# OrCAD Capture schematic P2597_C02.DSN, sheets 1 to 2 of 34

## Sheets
1 33_Buttons and Mechanical: size Custom
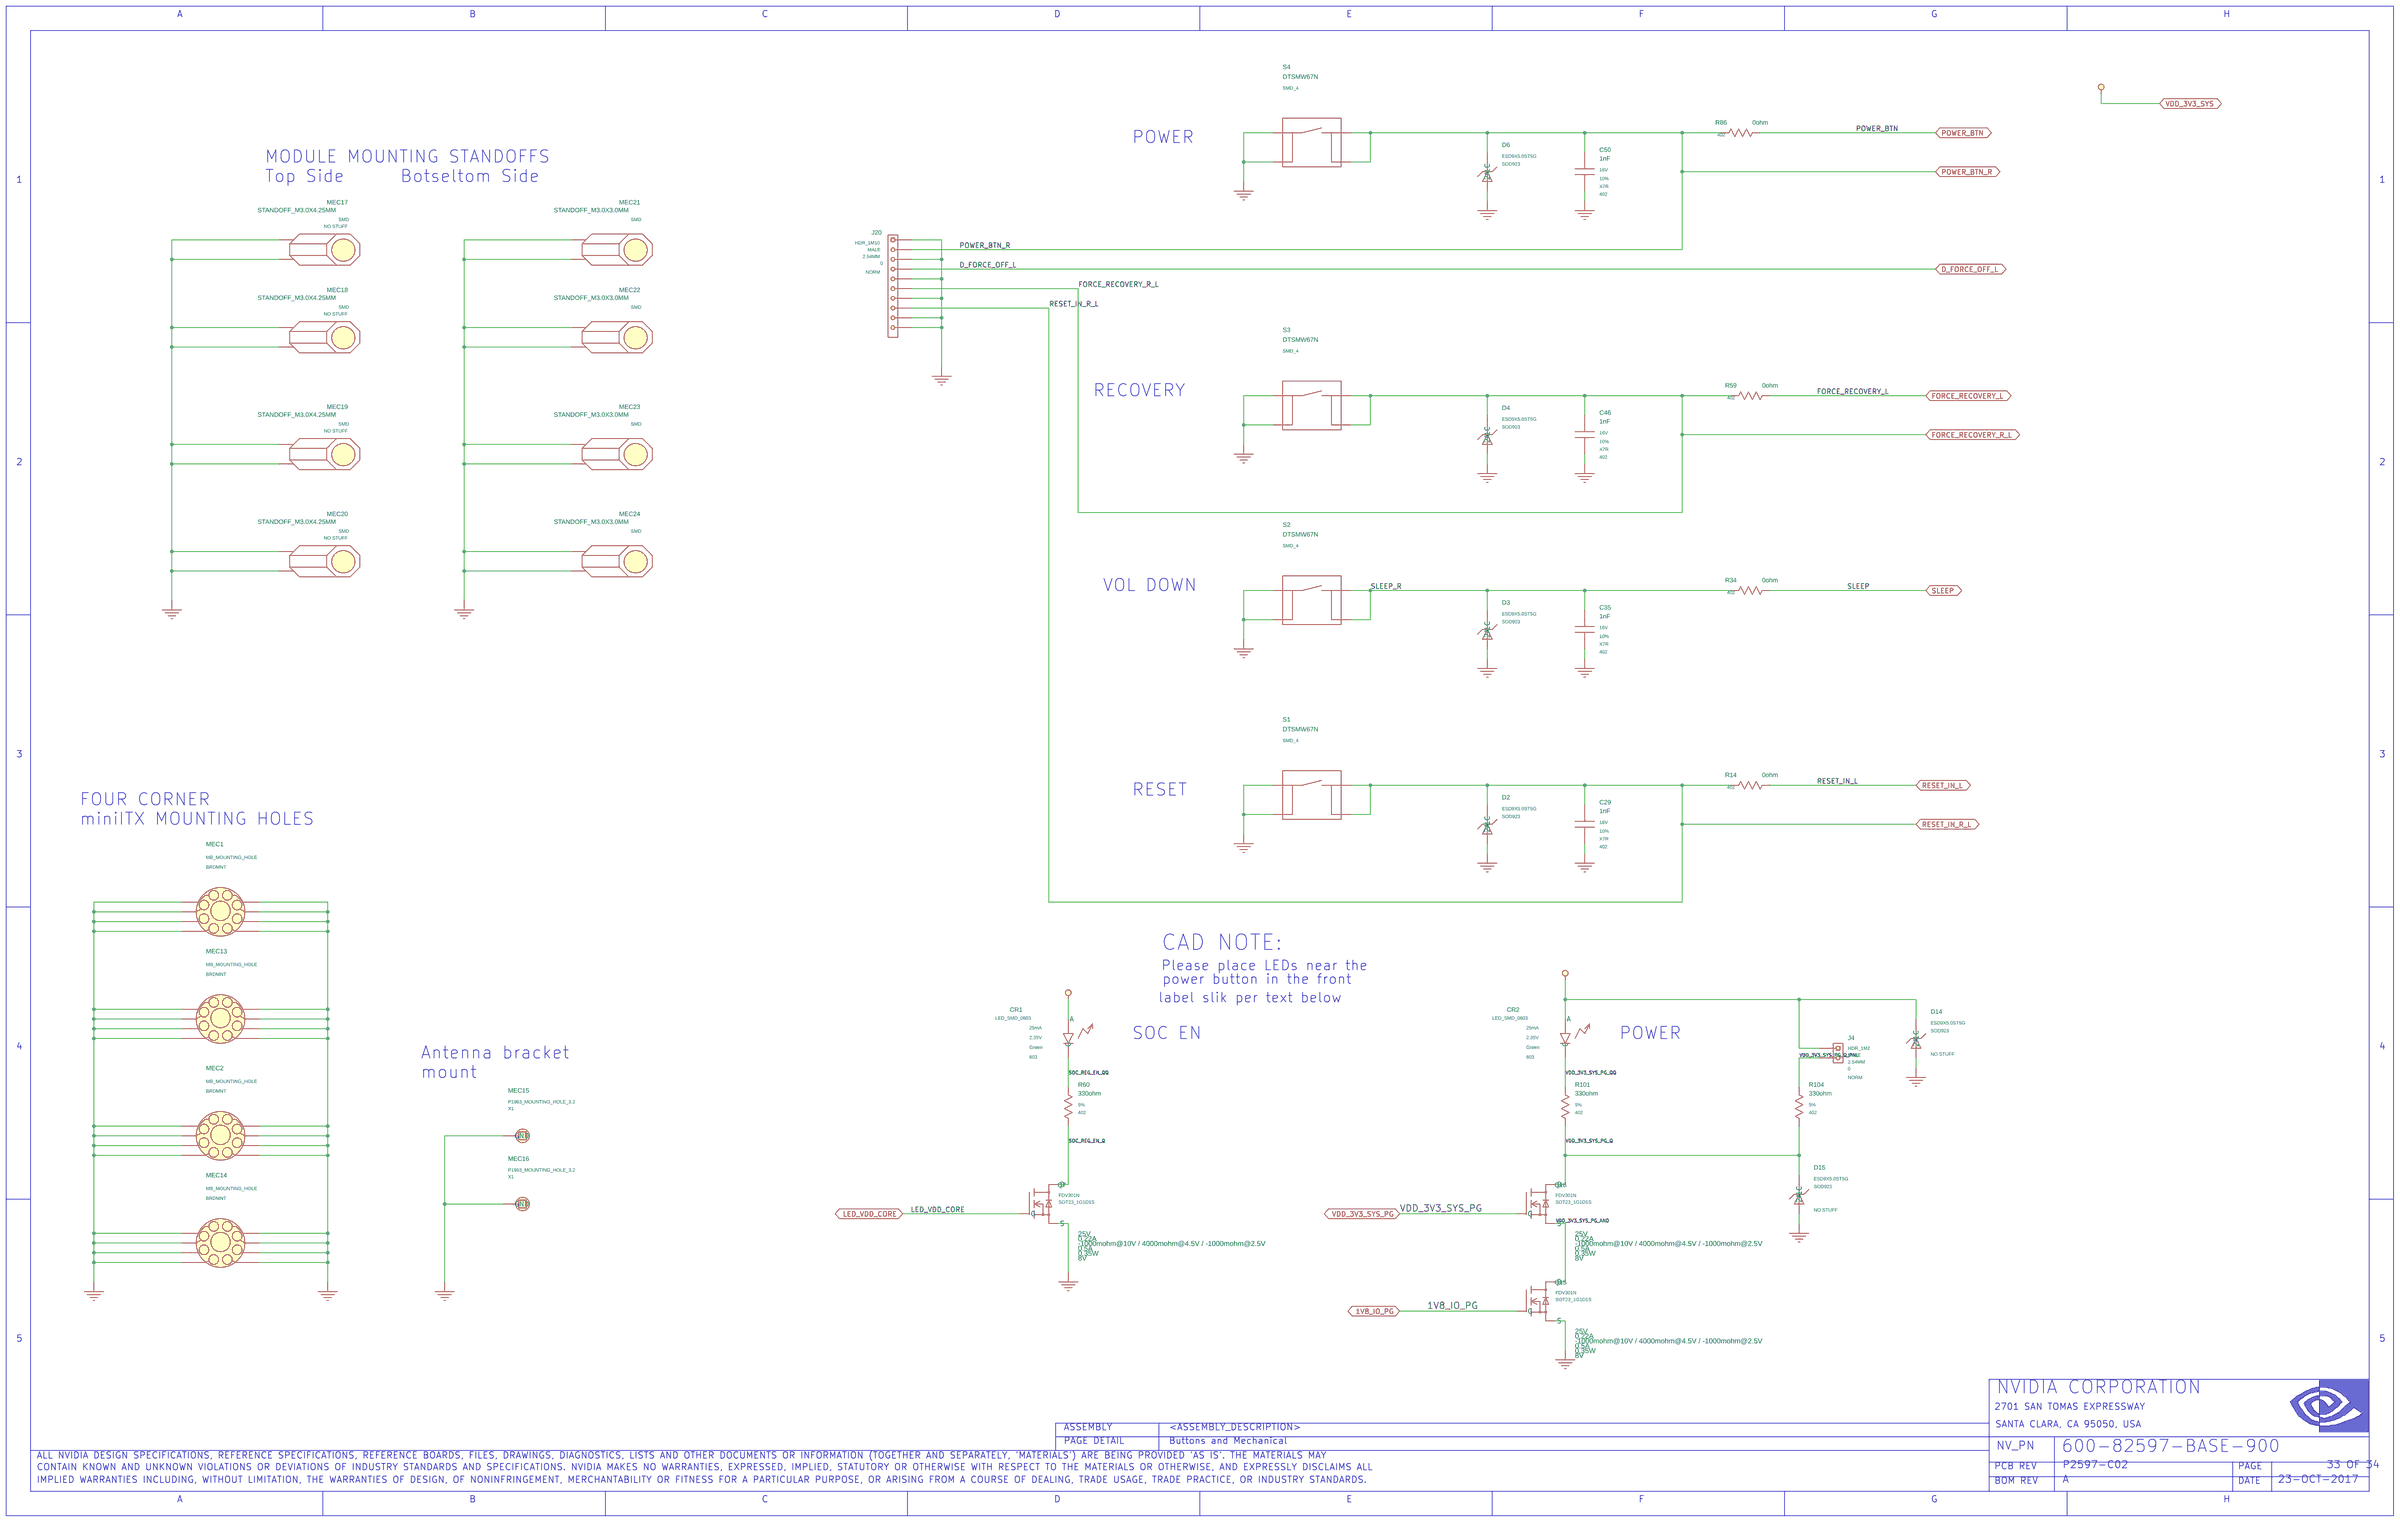
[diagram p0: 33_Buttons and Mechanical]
2 32_Power Monitor II: size Custom
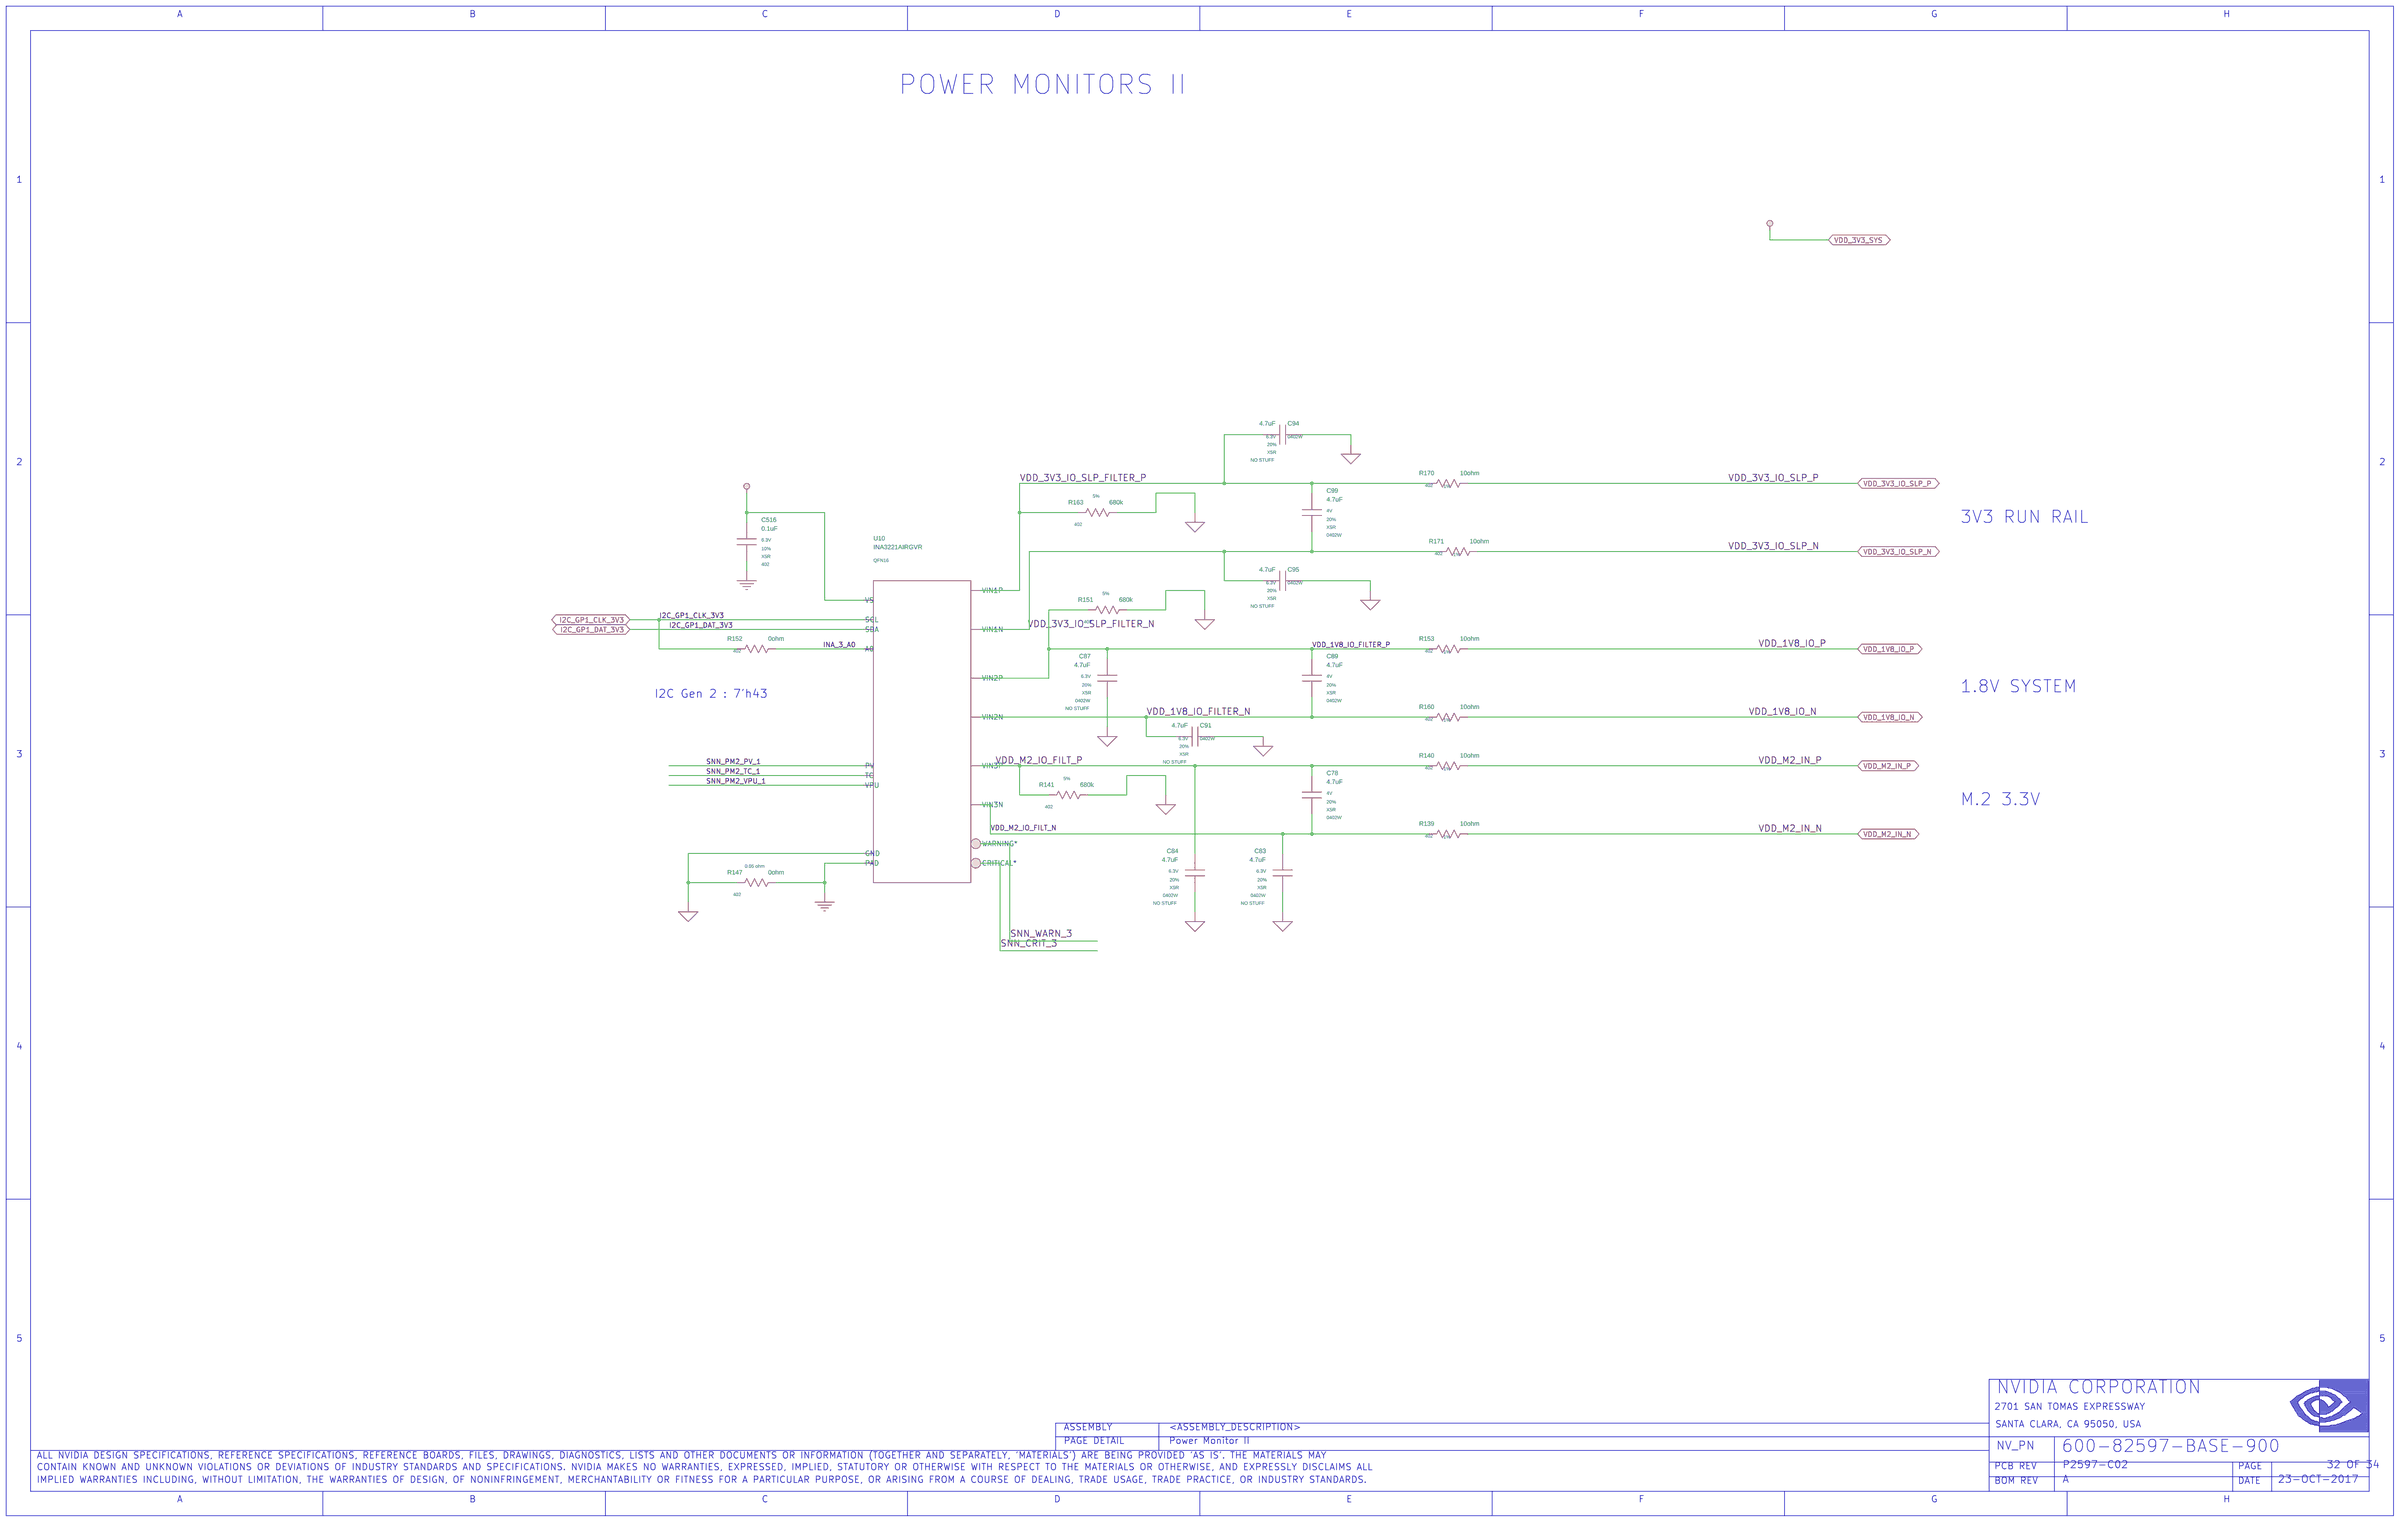
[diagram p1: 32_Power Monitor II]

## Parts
sheet 32_Power Monitor II
C78  4.7uF  [0402_LARGE]
C83  4.7uF  [0402_LARGE]
C84  4.7uF  [0402_LARGE]
C87  4.7uF  [0402_LARGE]
C89  4.7uF  [0402_LARGE]
C91  4.7uF  [0402_LARGE]
C94  4.7uF  [0402_LARGE]
C95  4.7uF  [0402_LARGE]
C99  4.7uF  [0402_LARGE]
C516  0.1uF  [402]
R139  10ohm  [402]
R140  10ohm  [402]
R141  680k  [402]
R147  0ohm  [402]
R151  680k  [402]
R152  0ohm  [402]
R153  10ohm  [402]
R160  10ohm  [402]
R163  680k  [402]
R170  10ohm  [402]
R171  10ohm  [402]
U10  U_PWRMTR_INA3221  [QFN016Q_P065_0047_T022X022]
sheet 33_Buttons and Mechanical
C29  1nF  [402]
C35  1nF  [402]
C46  1nF  [402]
C50  1nF  [402]
CR1  LED  [LED_SMD_0603_ST]
CR2  LED  [LED_SMD_0603_ST]
D2  D_ESD  [DIODE_SMD_SOD923]
D3  D_ESD  [DIODE_SMD_SOD923]
D4  D_ESD  [DIODE_SMD_SOD923]
D6  D_ESD  [DIODE_SMD_SOD923]
D14  D_ESD  [DIODE_SMD_SOD923]
D15  D_ESD  [DIODE_SMD_SOD923]
J4  HDR_1X2  [CON_HDR_001X002_TH_ST_M_P025]
J20  HDR_1X10  [CON_HDR_001X010_TH_ST_M_P025]
MEC1  MOUNTING_HOLE  [MTH_MB_C300NP156_NEW]
MEC2  MOUNTING_HOLE  [MTH_MB_C300NP156_NEW]
MEC13  MOUNTING_HOLE  [MTH_MB_C300NP156_NEW]
MEC14  MOUNTING_HOLE  [MTH_MB_C300NP156_NEW]
MEC15  MOUNTING_HOLE  [MEC_HOLE_PTH_599C_INT422C_B701C320P]
MEC16  MOUNTING_HOLE  [MEC_HOLE_PTH_599C_INT422C_B701C320P]
MEC17  MEC_STANDOFF2  [MEC_HOLE_PEM_NTH_430P]
MEC18  MEC_STANDOFF2  [MEC_HOLE_PEM_NTH_430P]
MEC19  MEC_STANDOFF2  [MEC_HOLE_PEM_NTH_430P]
MEC20  MEC_STANDOFF2  [MEC_HOLE_PEM_NTH_430P]
MEC21  MEC_STANDOFF2  [MEC_HOLE_PEM_NTH_430P]
MEC22  MEC_STANDOFF2  [MEC_HOLE_PEM_NTH_430P]
MEC23  MEC_STANDOFF2  [MEC_HOLE_PEM_NTH_430P]
MEC24  MEC_STANDOFF2  [MEC_HOLE_PEM_NTH_430P]
Q7  Q_FET_N_ENH  [SOT23]
Q15  Q_FET_N_ENH  [SOT23]
Q16  Q_FET_N_ENH  [SOT23]
R14  0ohm  [402]
R34  0ohm  [402]
R59  0ohm  [402]
R60  330ohm  [402]
R86  0ohm  [402]
R101  330ohm  [402]
R104  330ohm  [402]
S1  SW_SPST_PB  [SW_04_SMD_ST_1XONOFF_072X040]
S2  SW_SPST_PB  [SW_04_SMD_ST_1XONOFF_072X040]
S3  SW_SPST_PB  [SW_04_SMD_ST_1XONOFF_072X040]
S4  SW_SPST_PB  [SW_04_SMD_ST_1XONOFF_072X040]

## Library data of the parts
C78 = C: ASSEMBLY: PWR_MON; CDS_LIB: discrete; CDS_PART_NAME: C_0402W-4.7UF,X5R,20%,4V,039-0145-000; CDS_PHYS_PART_NAME: C_0402W-4.7UF,X5R,20%,4V,039-0145-000-039-0145-000,4.7UF; CDS_SEC: 1; DEVICE_TYPENAME: C_0402W-47UFX5R204V039-0145-000-039-0145-00047UF; DRAWING: @P2597_C02_LIB.P2597_C02(SCH_1):PAGE32; MAT: X5R; MAX_VOLTAGE: 4V; NO_XNET_CONNECTION: 1; NV_PN: 039-0145-000; PACK_TYPE: 0402W; PATH: I27; PHYS_PAGE: 32; ROT: 0; SEC: 1; SIGNAL_MODEL: DEFAULT_CAPACITOR_4.7e+06pF_2_1; TOL: 20%; VER: 1; XY: (-5450,3550)
C83 = C: ASSEMBLY: PWR_MON; CDS_LIB: discrete; CDS_PART_NAME: C_0402W-4.7UF,X5R,20%,6.3V,039-0188-000; CDS_PHYS_PART_NAME: C_0402W-4.7UF,X5R,20%,6.3V,039-0188-000-039-0188-000,4.7UF; CDS_SEC: 1; DEVICE_TYPENAME: C_0402W-47UFX5R2063V039-0188-000-039-0188-00047UF; DRAWING: @P2597_C02_LIB.P2597_C02(SCH_1):PAGE32; MAT: X5R; MAX_VOLTAGE: 6.3V; NV_PN: 039-0188-000; PACK_TYPE: 0402W; PATH: I99; PHYS_PAGE: 32; ROT: 2; SEC: 1; SEC_TYPE: 0402W; SIGNAL_MODEL: nv_cap; SKU: NO STUFF; TOL: 20%; VER: 1; XY: (-5600,3150)
C84 = C: ASSEMBLY: PWR_MON; CDS_LIB: discrete; CDS_PART_NAME: C_0402W-4.7UF,X5R,20%,6.3V,039-0188-000; CDS_PHYS_PART_NAME: C_0402W-4.7UF,X5R,20%,6.3V,039-0188-000-039-0188-000,4.7UF; CDS_SEC: 1; DEVICE_TYPENAME: C_0402W-47UFX5R2063V039-0188-000-039-0188-00047UF; DRAWING: @P2597_C02_LIB.P2597_C02(SCH_1):PAGE32; MAT: X5R; MAX_VOLTAGE: 6.3V; NV_PN: 039-0188-000; PACK_TYPE: 0402W; PATH: I98; PHYS_PAGE: 32; ROT: 2; SEC: 1; SEC_TYPE: 0402W; SIGNAL_MODEL: nv_cap; SKU: NO STUFF; TOL: 20%; VER: 1; XY: (-6050,3150)
C87 = C: ASSEMBLY: PWR_MON; CDS_LIB: discrete; CDS_PART_NAME: C_0402W-4.7UF,X5R,20%,6.3V,039-0188-000; CDS_PHYS_PART_NAME: C_0402W-4.7UF,X5R,20%,6.3V,039-0188-000-039-0188-000,4.7UF; CDS_SEC: 1; DEVICE_TYPENAME: C_0402W-47UFX5R2063V039-0188-000-039-0188-00047UF; DRAWING: @P2597_C02_LIB.P2597_C02(SCH_1):PAGE32; MAT: X5R; MAX_VOLTAGE: 6.3V; NV_PN: 039-0188-000; PACK_TYPE: 0402W; PATH: I102; PHYS_PAGE: 32; ROT: 2; SEC: 1; SEC_TYPE: 0402W; SIGNAL_MODEL: DEFAULT_CAPACITOR_100000pF_2_1; SKU: NO STUFF; TOL: 20%; VER: 1; XY: (-6500,4150)
C89 = C: ASSEMBLY: PWR_MON; CDS_LIB: discrete; CDS_PART_NAME: C_0402W-4.7UF,X5R,20%,4V,039-0145-000; CDS_PHYS_PART_NAME: C_0402W-4.7UF,X5R,20%,4V,039-0145-000-039-0145-000,4.7UF; CDS_SEC: 1; DEVICE_TYPENAME: C_0402W-47UFX5R204V039-0145-000-039-0145-00047UF; DRAWING: @P2597_C02_LIB.P2597_C02(SCH_1):PAGE32; MAT: X5R; MAX_VOLTAGE: 4V; NO_XNET_CONNECTION: 1; NV_PN: 039-0145-000; PACK_TYPE: 0402W; PATH: I28; PHYS_PAGE: 32; ROT: 0; SEC: 1; SIGNAL_MODEL: DEFAULT_CAPACITOR_4.7e+06pF_2_1; TOL: 20%; VER: 1; XY: (-5450,4150)
C91 = C#1: ASSEMBLY: PWR_MON; CDS_LIB: discrete; CDS_PART_NAME: C_0402W-4.7UF,X5R,20%,6.3V,039-0188-000; CDS_PHYS_PART_NAME: C_0402W-4.7UF,X5R,20%,6.3V,039-0188-000-039-0188-000,4.7UF; CDS_SEC: 1; CHIPS_PART_NAME: C; DEVICE_TYPENAME: C_0402W-47UFX5R2063V039-0188-000-039-0188-00047UF; DRAWING: @P2597_C02_LIB.P2597_C02(SCH_1):PAGE32; MAT: X5R; MAX_VOLTAGE: 6.3V; NV_PN: 039-0188-000; PACK_TYPE: 0402W; PATH: I103; PHYS_PAGE: 32; ROT: 2; SEC: 1; SIGNAL_MODEL: DEFAULT_CAPACITOR_100000pF_2_1; SKU: NO STUFF; TOL: 20%; VER: 2; XY: (-6050,3850)
C94 = C#1: ASSEMBLY: PWR_MON; CDS_LIB: discrete; CDS_PART_NAME: C_0402W-4.7UF,X5R,20%,6.3V,039-0188-000; CDS_PHYS_PART_NAME: C_0402W-4.7UF,X5R,20%,6.3V,039-0188-000-039-0188-000,4.7UF; CDS_SEC: 1; CHIPS_PART_NAME: C; DEVICE_TYPENAME: C_0402W-47UFX5R2063V039-0188-000-039-0188-00047UF; DRAWING: @P2597_C02_LIB.P2597_C02(SCH_1):PAGE32; MAT: X5R; MAX_VOLTAGE: 6.3V; NV_PN: 039-0188-000; PACK_TYPE: 0402W; PATH: I87; PHYS_PAGE: 32; ROT: 2; SEC: 1; SEC_TYPE: 0402W; SIGNAL_MODEL: nv_cap; SKU: NO STUFF; TOL: 20%; VER: 2; XY: (-5600,5400)
C95 = C#1: ASSEMBLY: PWR_MON; CDS_LIB: discrete; CDS_PART_NAME: C_0402W-4.7UF,X5R,20%,6.3V,039-0188-000; CDS_PHYS_PART_NAME: C_0402W-4.7UF,X5R,20%,6.3V,039-0188-000-039-0188-000,4.7UF; CDS_SEC: 1; CHIPS_PART_NAME: C; DEVICE_TYPENAME: C_0402W-47UFX5R2063V039-0188-000-039-0188-00047UF; DRAWING: @P2597_C02_LIB.P2597_C02(SCH_1):PAGE32; MAT: X5R; MAX_VOLTAGE: 6.3V; NV_PN: 039-0188-000; PACK_TYPE: 0402W; PATH: I88; PHYS_PAGE: 32; ROT: 2; SEC: 1; SIGNAL_MODEL: DEFAULT_CAPACITOR_100000pF_2_1; SKU: NO STUFF; TOL: 20%; VER: 2; XY: (-5600,4650)
C99 = C: ASSEMBLY: PWR_MON; CDS_LIB: discrete; CDS_PART_NAME: C_0402W-4.7UF,X5R,20%,4V,039-0145-000; CDS_PHYS_PART_NAME: C_0402W-4.7UF,X5R,20%,4V,039-0145-000-039-0145-000,4.7UF; CDS_SEC: 1; DEVICE_TYPENAME: C_0402W-47UFX5R204V039-0145-000-039-0145-00047UF; DRAWING: @P2597_C02_LIB.P2597_C02(SCH_1):PAGE32; MAT: X5R; MAX_VOLTAGE: 4V; NO_XNET_CONNECTION: 1; NV_PN: 039-0145-000; PACK_TYPE: 0402W; PATH: I32; PHYS_PAGE: 32; ROT: 0; SEC: 1; SEC_TYPE: 0402W; SIGNAL_MODEL: DEFAULT_CAPACITOR_4.7e+06pF_2_1; TOL: 20%; VER: 1; XY: (-5450,5000)
C516 = C: ASSEMBLY: PWR_MON; CDS_LIB: discrete; CDS_PART_NAME: C_0402-0.1UF,X5R,10%,6.3V,039-0007-000; CDS_PHYS_PART_NAME: C_0402-0.1UF,X5R,10%,6.3V,039-0007-000-0.1UF,039-0007-000; CDS_SEC: 1; DEVICE_TYPENAME: C_0402-01UFX5R1063V039-0007-000-01UF039-0007-000; DRAWING: @P2597_C02_LIB.P2597_C02(SCH_1):PAGE32; MAT: X5R; MAX_VOLTAGE: 6.3V; NV_PN: 039-0007-000; PATH: I7; PHYS_PAGE: 32; ROT: 0; SEC: 1; SIGNAL_MODEL: DEFAULT_CAPACITOR_100000pF_2_1; TOL: 10%; VER: 1; XY: (-8350,4850)
R139 = R: ASSEMBLY: PWR_MON; CDS_LIB: discrete; CDS_PART_NAME: R_0402-10OHM,1 %,62.5MW,195-0001-000; CDS_PHYS_PART_NAME: R_0402-10OHM,1 %,62.5MW,195-0001-000-10OHM,195-0001-000; CDS_SEC: 1; DEVICE_TYPENAME: R_0402-10OHM1625MW195-0001-000-10OHM195-0001-000; DRAWING: @P2597_C02_LIB.P2597_C02(SCH_1):PAGE32; MAX_WATTAGE: 62.5mW; NV_PN: 195-0001-000; PATH: I26; PHYS_PAGE: 32; ROT: 0; SEC: 1; SIGNAL_MODEL: nv_res; TOL: 1%; VER: 1; XY: (-4750,3350)
R140 = R: ASSEMBLY: PWR_MON; CDS_LIB: discrete; CDS_PART_NAME: R_0402-10OHM,1 %,62.5MW,195-0001-000; CDS_PHYS_PART_NAME: R_0402-10OHM,1 %,62.5MW,195-0001-000-10OHM,195-0001-000; CDS_SEC: 1; DEVICE_TYPENAME: R_0402-10OHM1625MW195-0001-000-10OHM195-0001-000; DRAWING: @P2597_C02_LIB.P2597_C02(SCH_1):PAGE32; MAX_WATTAGE: 62.5mW; NV_PN: 195-0001-000; PATH: I29; PHYS_PAGE: 32; ROT: 0; SEC: 1; SIGNAL_MODEL: nv_res; TOL: 1%; VER: 1; XY: (-4750,3700)
R141 = R: ASSEMBLY: PWR_MON; CDS_LIB: discrete; CDS_PART_NAME: R_0402-680K,5 %,62.5MW,195-0628-000; CDS_PHYS_PART_NAME: R_0402-680K,5 %,62.5MW,195-0628-000-195-0628-000,680K; CDS_SEC: 1; DEVICE_TYPENAME: R_0402-680K5625MW195-0628-000-195-0628-000680K; DRAWING: @P2597_C02_LIB.P2597_C02(SCH_1):PAGE32; MAX_WATTAGE: 62.5mW; NV_PN: 195-0628-000; PATH: I120; PHYS_PAGE: 32; ROT: 0; SEC: 1; SIGNAL_MODEL: nv_res; TOL: 5%; VER: 1; XY: (-6700,3550)
R147 = R: ASSEMBLY: PWR_MON; CDS_LIB: discrete; CDS_PART_NAME: R_0402-0OHM,0.05 OHM,62.5MW,195-2655-000; CDS_PHYS_PART_NAME: R_0402-0OHM,0.05 OHM,62.5MW,195-2655-000-0OHM,195-2655-000; CDS_SEC: 1; DEVICE_TYPENAME: R_0402-0OHM005OHM625MW195-2655-000-0OHM195-2655-000; DRAWING: @P2597_C02_LIB.P2597_C02(SCH_1):PAGE32; MAX_WATTAGE: 62.5mW; NV_PN: 195-2655-000; PATH: I95; PHYS_PAGE: 32; ROT: 0; SEC: 1; SIGNAL_MODEL: nv_res; TOL: 0.05 ohm; VER: 1; XY: (-8300,3100)
R151 = R: ASSEMBLY: PWR_MON; CDS_LIB: discrete; CDS_PART_NAME: R_0402-680K,5 %,62.5MW,195-0628-000; CDS_PHYS_PART_NAME: R_0402-680K,5 %,62.5MW,195-0628-000-195-0628-000,680K; CDS_SEC: 1; DEVICE_TYPENAME: R_0402-680K5625MW195-0628-000-195-0628-000680K; DRAWING: @P2597_C02_LIB.P2597_C02(SCH_1):PAGE32; MAX_WATTAGE: 62.5mW; NV_PN: 195-0628-000; PATH: I118; PHYS_PAGE: 32; ROT: 0; SEC: 1; SIGNAL_MODEL: nv_res; TOL: 5%; VER: 1; XY: (-6500,4500)
R152 = R: ASSEMBLY: PWR_MON; CDS_LIB: discrete; CDS_PART_NAME: R_0402-0OHM,0.05 OHM,62.5MW,195-2655-000; CDS_PHYS_PART_NAME: R_0402-0OHM,0.05 OHM,62.5MW,195-2655-000-0OHM,195-2655-000; CDS_SEC: 1; DEVICE_TYPENAME: R_0402-0OHM005OHM625MW195-2655-000-0OHM195-2655-000; DRAWING: @P2597_C02_LIB.P2597_C02(SCH_1):PAGE32; MAX_WATTAGE: 62.5mW; NV_PN: 195-2655-000; PATH: I108; PHYS_PAGE: 32; ROT: 0; SEC: 1; SIGNAL_MODEL: nv_res; TOL: 0.05 ohm; VER: 1; XY: (-8300,4300)
R153 = R: ASSEMBLY: PWR_MON; CDS_LIB: discrete; CDS_PART_NAME: R_0402-10OHM,1 %,62.5MW,195-0001-000; CDS_PHYS_PART_NAME: R_0402-10OHM,1 %,62.5MW,195-0001-000-10OHM,195-0001-000; CDS_SEC: 1; DEVICE_TYPENAME: R_0402-10OHM1625MW195-0001-000-10OHM195-0001-000; DRAWING: @P2597_C02_LIB.P2597_C02(SCH_1):PAGE32; MAX_WATTAGE: 62.5mW; NV_PN: 195-0001-000; PATH: I31; PHYS_PAGE: 32; ROT: 0; SEC: 1; SIGNAL_MODEL: nv_res; TOL: 1%; VER: 1; XY: (-4750,4300)
R160 = R: ASSEMBLY: PWR_MON; CDS_LIB: discrete; CDS_PART_NAME: R_0402-10OHM,1 %,62.5MW,195-0001-000; CDS_PHYS_PART_NAME: R_0402-10OHM,1 %,62.5MW,195-0001-000-10OHM,195-0001-000; CDS_SEC: 1; DEVICE_TYPENAME: R_0402-10OHM1625MW195-0001-000-10OHM195-0001-000; DRAWING: @P2597_C02_LIB.P2597_C02(SCH_1):PAGE32; MAX_WATTAGE: 62.5mW; NV_PN: 195-0001-000; PATH: I30; PHYS_PAGE: 32; ROT: 0; SEC: 1; SIGNAL_MODEL: nv_res; TOL: 1%; VER: 1; XY: (-4750,3950)
R163 = R: ASSEMBLY: PWR_MON; CDS_LIB: discrete; CDS_PART_NAME: R_0402-680K,5 %,62.5MW,195-0628-000; CDS_PHYS_PART_NAME: R_0402-680K,5 %,62.5MW,195-0628-000-195-0628-000,680K; CDS_SEC: 1; DEVICE_TYPENAME: R_0402-680K5625MW195-0628-000-195-0628-000680K; DRAWING: @P2597_C02_LIB.P2597_C02(SCH_1):PAGE32; MAX_WATTAGE: 62.5mW; NV_PN: 195-0628-000; PATH: I115; PHYS_PAGE: 32; ROT: 0; SEC: 1; SIGNAL_MODEL: nv_res; TOL: 5%; VER: 1; XY: (-6550,5000)
R170 = R: ASSEMBLY: PWR_MON; CDS_LIB: discrete; CDS_PART_NAME: R_0402-10OHM,1 %,62.5MW,195-0001-000; CDS_PHYS_PART_NAME: R_0402-10OHM,1 %,62.5MW,195-0001-000-10OHM,195-0001-000; CDS_SEC: 1; DEVICE_TYPENAME: R_0402-10OHM1625MW195-0001-000-10OHM195-0001-000; DRAWING: @P2597_C02_LIB.P2597_C02(SCH_1):PAGE32; MAX_WATTAGE: 62.5mW; NV_PN: 195-0001-000; PATH: I34; PHYS_PAGE: 32; ROT: 0; SEC: 1; SIGNAL_MODEL: nv_res; TOL: 1%; VER: 1; XY: (-4750,5150)
R171 = R: ASSEMBLY: PWR_MON; CDS_LIB: discrete; CDS_PART_NAME: R_0402-10OHM,1 %,62.5MW,195-0001-000; CDS_PHYS_PART_NAME: R_0402-10OHM,1 %,62.5MW,195-0001-000-10OHM,195-0001-000; CDS_SEC: 1; DEVICE_TYPENAME: R_0402-10OHM1625MW195-0001-000-10OHM195-0001-000; DRAWING: @P2597_C02_LIB.P2597_C02(SCH_1):PAGE32; MAX_WATTAGE: 62.5mW; NV_PN: 195-0001-000; PATH: I33; PHYS_PAGE: 32; ROT: 0; SEC: 1; SIGNAL_MODEL: nv_res; TOL: 1%; VER: 1; XY: (-4700,4800)
U10 = U_PWRMTR_INA3221: ASSEMBLY: PWR_MON; CDS_LIB: digital; CDS_PART_NAME: U_PWRMTR_INA3221_QFN16-INA3221AIRGVR,-9999V..9999V,-9999V..9999V,9999A,MONITOR,115-1066-000; CDS_PHYS_PART_NAME: U_PWRMTR_INA3221_QFN16-INA3221AIRGVR,-9999V..9999V,-9999V..9999V,9999A,MONITOR,115-1066-000-115-1066-000; CDS_SEC: 1; DEVICE_TYPENAME: U_PWRMTR_INA3221_QFN16-INA3221AIRGVR-9999V9999V-9999V9999V9999AMONITOR115-1066-000-115-1066-000; DRAWING: @P2597_C02_LIB.P2597_C02(SCH_1):PAGE32; MAX_CURRENT: 9999A; MAX_VOLTAGE: -9999V..9999V; NV_NAME: INA3221AIRGVR; NV_PN: 115-1066-000; OUTPUT_VOLTAGE: -9999V..9999V; PACK_TYPE: QFN16; PATH: I5; PHYS_PAGE: 32; ROT: 0; SEC: 1; SEC_TYPE: QFN16; TYPE: Monitor; VER: 1; XY: (-7450,3900)
C29 = C: ASSEMBLY: BUTTONS; CDS_LIB: discrete; CDS_PART_NAME: C_0402-1NF,X7R,10%,16V,036-0012-000; CDS_PHYS_PART_NAME: C_0402-1NF,X7R,10%,16V,036-0012-000-036-0012-000,1NF; CDS_SEC: 1; DEVICE_TYPENAME: C_0402-1NFX7R1016V036-0012-000-036-0012-0001NF; DRAWING: @P2597_C02_LIB.P2597_C02(SCH_1):PAGE33; MAT: X7R; MAX_VOLTAGE: 16V; NV_PN: 036-0012-000; PATH: I36; PHYS_PAGE: 33; ROT: 0; SEC: 1; SIGNAL_MODEL: nv_cap; TOL: 10%; VER: 1; XY: (-4050,3400)
C35 = C: ASSEMBLY: BUTTONS; CDS_LIB: discrete; CDS_PART_NAME: C_0402-1NF,X7R,10%,16V,036-0012-000; CDS_PHYS_PART_NAME: C_0402-1NF,X7R,10%,16V,036-0012-000-036-0012-000,1NF; CDS_SEC: 1; DEVICE_TYPENAME: C_0402-1NFX7R1016V036-0012-000-036-0012-0001NF; DRAWING: @P2597_C02_LIB.P2597_C02(SCH_1):PAGE33; MAT: X7R; MAX_VOLTAGE: 16V; NV_PN: 036-0012-000; PATH: I102; PHYS_PAGE: 33; ROT: 0; SEC: 1; SIGNAL_MODEL: DEFAULT_CAPACITOR_1000pF_2_1; TOL: 10%; VER: 1; XY: (-4050,4400)
C46 = C: ASSEMBLY: BUTTONS; CDS_LIB: discrete; CDS_PART_NAME: C_0402-1NF,X7R,10%,16V,036-0012-000; CDS_PHYS_PART_NAME: C_0402-1NF,X7R,10%,16V,036-0012-000-036-0012-000,1NF; CDS_SEC: 1; DEVICE_TYPENAME: C_0402-1NFX7R1016V036-0012-000-036-0012-0001NF; DRAWING: @P2597_C02_LIB.P2597_C02(SCH_1):PAGE33; MAT: X7R; MAX_VOLTAGE: 16V; NV_PN: 036-0012-000; PATH: I30; PHYS_PAGE: 33; ROT: 0; SEC: 1; SIGNAL_MODEL: DEFAULT_CAPACITOR_1000pF_2_1; TOL: 10%; VER: 1; XY: (-4050,5400)
C50 = C: ASSEMBLY: BUTTONS; CDS_LIB: discrete; CDS_PART_NAME: C_0402-1NF,X7R,10%,16V,036-0012-000; CDS_PHYS_PART_NAME: C_0402-1NF,X7R,10%,16V,036-0012-000-036-0012-000,1NF; CDS_SEC: 1; DEVICE_TYPENAME: C_0402-1NFX7R1016V036-0012-000-036-0012-0001NF; DRAWING: @P2597_C02_LIB.P2597_C02(SCH_1):PAGE33; MAT: X7R; MAX_VOLTAGE: 16V; NV_PN: 036-0012-000; PATH: I18; PHYS_PAGE: 33; ROT: 0; SEC: 1; SIGNAL_MODEL: nv_cap; TOL: 10%; VER: 1; XY: (-4050,6750)
CR1 = LED: ASSEMBLY: BUTTONS; CDS_LIB: discrete; CDS_PART_NAME: LED_0603-LED_SMD_0603,5V,60MA,2.35V,25MA,GREEN,092-0073-000; CDS_PHYS_PART_NAME: LED_0603-LED_SMD_0603,5V,60MA,2.35V,25MA,GREEN,092-0073-000-092-0073-000; CDS_SEC: 1; CONTINUOUS_CURRENT: 25mA; DEVICE_TYPENAME: LED_0603-LED_SMD_06035V60MA235V25MAGREEN092-0073-000-092-0073-000; DRAWING: @P2597_C02_LIB.P2597_C02(SCH_1):PAGE33; FORWARD_VOLTAGE: 2.35V; MAX_CURRENT: 60mA; MAX_VOLTAGE: 5V; NV_COLOR: Green; NV_NAME: LED_SMD_0603; NV_PN: 092-0073-000; PACK_TYPE: 603; PATH: I75; PHYS_PAGE: 33; ROT: 0; SEC: 1; SEC_TYPE: 603; VER: 1; XY: (-6700,2300)
CR2 = LED: ASSEMBLY: BUTTONS; CDS_LIB: discrete; CDS_PART_NAME: LED_0603-LED_SMD_0603,5V,60MA,2.35V,25MA,GREEN,092-0073-000; CDS_PHYS_PART_NAME: LED_0603-LED_SMD_0603,5V,60MA,2.35V,25MA,GREEN,092-0073-000-092-0073-000; CDS_SEC: 1; CONTINUOUS_CURRENT: 25mA; DEVICE_TYPENAME: LED_0603-LED_SMD_06035V60MA235V25MAGREEN092-0073-000-092-0073-000; DRAWING: @P2597_C02_LIB.P2597_C02(SCH_1):PAGE33; FORWARD_VOLTAGE: 2.35V; MAX_CURRENT: 60mA; MAX_VOLTAGE: 5V; NV_COLOR: Green; NV_NAME: LED_SMD_0603; NV_PN: 092-0073-000; PACK_TYPE: 603; PATH: I52; PHYS_PAGE: 33; ROT: 0; SEC: 1; SEC_TYPE: 603; VER: 1; XY: (-4150,2300)
D2 = D_ESD#1: ASSEMBLY: BUTTONS; BREAKDOWN_VOLTAGE_MIN_TYP: 6.2V; CAPACITANCE_MAX_TYP: 65pF; CDS_LIB: discrete; CDS_PART_NAME: D_ESD_SOD923-ESD9X5.0ST5G,1 LINE,UNI-DIRECTIONAL,5V,1UA,6.2V,12.3V@8.7A,65PF,090-0134-000; CDS_PHYS_PART_NAME: D_ESD_SOD923-ESD9X5.0ST5G,1 LINE,UNI-DIRECTIONAL,5V,1UA,6.2V,12.3V@8.7A,65PF,090-0134-000-090-0134-000; CDS_SEC: 1; CLAMPING_VOLTAGE: 12.3V@8.7A; CONFIGURATION: 1 Line; DEVICE_TYPENAME: D_ESD_SOD923-ESD9X50ST5G1LINEUNI-DIRECTIONAL5V1UA62V123V87A65PF090-0134-000-090-0134-000; DRAWING: @P2597_C02_LIB.P2597_C02(SCH_1):PAGE33; MAX_REVERSE_LEAKAGE_CURRENT: 1uA; MAX_REVERSE_VOLTAGE: 5V; NV_NAME: ESD9X5.0ST5G; NV_PN: 090-0134-000; PACK_TYPE: SOD923; PATH: I38; PHYS_PAGE: 33; POLARITY: Uni-Directional; ROT: 0; SEC: 1; VER: 5; XY: (-4550,3400)
D3 = D_ESD#1: ASSEMBLY: BUTTONS; BREAKDOWN_VOLTAGE_MIN_TYP: 6.2V; CAPACITANCE_MAX_TYP: 65pF; CDS_LIB: discrete; CDS_PART_NAME: D_ESD_SOD923-ESD9X5.0ST5G,1 LINE,UNI-DIRECTIONAL,5V,1UA,6.2V,12.3V@8.7A,65PF,090-0134-000; CDS_PHYS_PART_NAME: D_ESD_SOD923-ESD9X5.0ST5G,1 LINE,UNI-DIRECTIONAL,5V,1UA,6.2V,12.3V@8.7A,65PF,090-0134-000-090-0134-000; CDS_SEC: 1; CLAMPING_VOLTAGE: 12.3V@8.7A; CONFIGURATION: 1 Line; DEVICE_TYPENAME: D_ESD_SOD923-ESD9X50ST5G1LINEUNI-DIRECTIONAL5V1UA62V123V87A65PF090-0134-000-090-0134-000; DRAWING: @P2597_C02_LIB.P2597_C02(SCH_1):PAGE33; MAX_REVERSE_LEAKAGE_CURRENT: 1uA; MAX_REVERSE_VOLTAGE: 5V; NV_NAME: ESD9X5.0ST5G; NV_PN: 090-0134-000; PACK_TYPE: SOD923; PATH: I105; PHYS_PAGE: 33; POLARITY: Uni-Directional; ROT: 0; SEC: 1; VER: 5; XY: (-4550,4400)
D4 = D_ESD#1: ASSEMBLY: BUTTONS; BREAKDOWN_VOLTAGE_MIN_TYP: 6.2V; CAPACITANCE_MAX_TYP: 65pF; CDS_LIB: discrete; CDS_PART_NAME: D_ESD_SOD923-ESD9X5.0ST5G,1 LINE,UNI-DIRECTIONAL,5V,1UA,6.2V,12.3V@8.7A,65PF,090-0134-000; CDS_PHYS_PART_NAME: D_ESD_SOD923-ESD9X5.0ST5G,1 LINE,UNI-DIRECTIONAL,5V,1UA,6.2V,12.3V@8.7A,65PF,090-0134-000-090-0134-000; CDS_SEC: 1; CLAMPING_VOLTAGE: 12.3V@8.7A; CONFIGURATION: 1 Line; DEVICE_TYPENAME: D_ESD_SOD923-ESD9X50ST5G1LINEUNI-DIRECTIONAL5V1UA62V123V87A65PF090-0134-000-090-0134-000; DRAWING: @P2597_C02_LIB.P2597_C02(SCH_1):PAGE33; MAX_REVERSE_LEAKAGE_CURRENT: 1uA; MAX_REVERSE_VOLTAGE: 5V; NV_NAME: ESD9X5.0ST5G; NV_PN: 090-0134-000; PACK_TYPE: SOD923; PATH: I28; PHYS_PAGE: 33; POLARITY: Uni-Directional; ROT: 0; SEC: 1; VER: 5; XY: (-4550,5400)
D6 = D_ESD#1: ASSEMBLY: BUTTONS; BREAKDOWN_VOLTAGE_MIN_TYP: 6.2V; CAPACITANCE_MAX_TYP: 65pF; CDS_LIB: discrete; CDS_PART_NAME: D_ESD_SOD923-ESD9X5.0ST5G,1 LINE,UNI-DIRECTIONAL,5V,1UA,6.2V,12.3V@8.7A,65PF,090-0134-000; CDS_PHYS_PART_NAME: D_ESD_SOD923-ESD9X5.0ST5G,1 LINE,UNI-DIRECTIONAL,5V,1UA,6.2V,12.3V@8.7A,65PF,090-0134-000-090-0134-000; CDS_SEC: 1; CLAMPING_VOLTAGE: 12.3V@8.7A; CONFIGURATION: 1 Line; DEVICE_TYPENAME: D_ESD_SOD923-ESD9X50ST5G1LINEUNI-DIRECTIONAL5V1UA62V123V87A65PF090-0134-000-090-0134-000; DRAWING: @P2597_C02_LIB.P2597_C02(SCH_1):PAGE33; MAX_REVERSE_LEAKAGE_CURRENT: 1uA; MAX_REVERSE_VOLTAGE: 5V; NV_NAME: ESD9X5.0ST5G; NV_PN: 090-0134-000; PACK_TYPE: SOD923; PATH: I13; PHYS_PAGE: 33; POLARITY: Uni-Directional; ROT: 0; SEC: 1; VER: 5; XY: (-4550,6750)
D14 = D_ESD#1: ASSEMBLY: BUTTONS; BREAKDOWN_VOLTAGE_MIN_TYP: 6.2V; CAPACITANCE_MAX_TYP: 65pF; CDS_LIB: discrete; CDS_PART_NAME: D_ESD_SOD923-ESD9X5.0ST5G,1 LINE,UNI-DIRECTIONAL,5V,1UA,6.2V,12.3V@8.7A,65PF,090-0134-000; CDS_PHYS_PART_NAME: D_ESD_SOD923-ESD9X5.0ST5G,1 LINE,UNI-DIRECTIONAL,5V,1UA,6.2V,12.3V@8.7A,65PF,090-0134-000-090-0134-000; CDS_SEC: 1; CLAMPING_VOLTAGE: 12.3V@8.7A; CONFIGURATION: 1 Line; DEVICE_TYPENAME: D_ESD_SOD923-ESD9X50ST5G1LINEUNI-DIRECTIONAL5V1UA62V123V87A65PF090-0134-000-090-0134-000; DRAWING: @P2597_C02_LIB.P2597_C02(SCH_1):PAGE33; MAX_REVERSE_LEAKAGE_CURRENT: 1uA; MAX_REVERSE_VOLTAGE: 5V; NV_NAME: ESD9X5.0ST5G; NV_PN: 090-0134-000; PACK_TYPE: SOD923; PATH: I145; PHYS_PAGE: 33; POLARITY: Uni-Directional; ROT: 0; SEC: 1; SEC_TYPE: SOD923; SKU: NO STUFF; VER: 5; XY: (-2350,2300)
D15 = D_ESD#1: ASSEMBLY: BUTTONS; BREAKDOWN_VOLTAGE_MIN_TYP: 6.2V; CAPACITANCE_MAX_TYP: 65pF; CDS_LIB: discrete; CDS_PART_NAME: D_ESD_SOD923-ESD9X5.0ST5G,1 LINE,UNI-DIRECTIONAL,5V,1UA,6.2V,12.3V@8.7A,65PF,090-0134-000; CDS_PHYS_PART_NAME: D_ESD_SOD923-ESD9X5.0ST5G,1 LINE,UNI-DIRECTIONAL,5V,1UA,6.2V,12.3V@8.7A,65PF,090-0134-000-090-0134-000; CDS_SEC: 1; CLAMPING_VOLTAGE: 12.3V@8.7A; CONFIGURATION: 1 Line; DEVICE_TYPENAME: D_ESD_SOD923-ESD9X50ST5G1LINEUNI-DIRECTIONAL5V1UA62V123V87A65PF090-0134-000-090-0134-000; DRAWING: @P2597_C02_LIB.P2597_C02(SCH_1):PAGE33; MAX_REVERSE_LEAKAGE_CURRENT: 1uA; MAX_REVERSE_VOLTAGE: 5V; NV_NAME: ESD9X5.0ST5G; NV_PN: 090-0134-000; PACK_TYPE: SOD923; PATH: I143; PHYS_PAGE: 33; POLARITY: Uni-Directional; ROT: 0; SEC: 1; SEC_TYPE: SOD923; SKU: NO STUFF; VER: 5; XY: (-2950,1500)
J4 = HDR_1X2: ANGLE: 0; ASSEMBLY: BUTTONS; CDS_LIB: electro_mechanic; CDS_PART_NAME: HDR_1X2_NORM-HDR_1M2,MALE,2.54MM,0,NO,NO,NO,250V,3A,074-0117-000; CDS_PHYS_PART_NAME: HDR_1X2_NORM-HDR_1M2,MALE,2.54MM,0,NO,NO,NO,250V,3A,074-0117-000-074-0117-000; CDS_SEC: 1; DEVICE_TYPENAME: HDR_1X2_NORM-HDR_1M2MALE254MM0NONONO250V3A074-0117-000-074-0117-000; DRAWING: @P2597_C02_LIB.P2597_C02(SCH_1):PAGE33; GENDER: MALE; LATCHING: NO; MAX_CURRENT: 3A; MAX_VOLTAGE: 250V; NV_NAME: HDR_1M2; NV_PN: 074-0117-000; PACK_TYPE: NORM; PATH: I123; PHYS_PAGE: 33; PITCH: 2.54MM; REFLOW: NO; ROT: 0; SEC: 1; SEC_TYPE: NORM; SHROUDED: NO; VER: 1; XY: (-2750,2250)
J20 = HDR_1X10#1: ANGLE: 0; ASSEMBLY: BUTTONS; CDS_LIB: electro_mechanic; CDS_PART_NAME: HDR_1X10_NORM-HDR_1M10,MALE,2.54MM,0,NO,N/A,NO,3A,3A,080-0010-000; CDS_PHYS_PART_NAME: HDR_1X10_NORM-HDR_1M10,MALE,2.54MM,0,NO,N/A,NO,3A,3A,080-0010-000-080-0010-000; CDS_SEC: 1; DEVICE_TYPENAME: HDR_1X10_NORM-HDR_1M10MALE254MM0NONANO3A3A080-0010-000-080-0010-000; DRAWING: @P2597_C02_LIB.P2597_C02(SCH_1):PAGE33; GENDER: MALE; LATCHING: NO; MAX_CURRENT: 3A; MAX_VOLTAGE: 3A; NV_NAME: HDR_1M10; NV_PN: 080-0010-000; PACK_TYPE: NORM; PATH: I150; PHYS_PAGE: 33; PITCH: 2.54MM; REFLOW: NO; ROT: 2; SEC: 1; SEC_TYPE: NORM; SHROUDED: N/A; VER: 1; XY: (-7600,6400)
MEC1 = MOUNTING_HOLE#1: CDS_LIB: mechanic; CDS_PART_NAME: MOUNTING_HOLE_BRDMNT-MB_MOUNTING_HOLE; CDS_PHYS_PART_NAME: MOUNTING_HOLE_BRDMNT-MB_MOUNTING_HOLE; CDS_SEC: 1; DEVICE_TYPENAME: MOUNTING_HOLE_BRDMNT-MB_MOUNTING_HOLE; DRAWING: @P2597_C02_LIB.P2597_C02(SCH_1):PAGE33; NV_NAME: MB_MOUNTING_HOLE; PACK_TYPE: BRDMNT; PATH: I118; PHYS_PAGE: 33; ROT: 0; SEC: 1; SEC_TYPE: BRDMNT; VER: 2; XY: (-11050,2950)
MEC2 = MOUNTING_HOLE#1: CDS_LIB: mechanic; CDS_PART_NAME: MOUNTING_HOLE_BRDMNT-MB_MOUNTING_HOLE; CDS_PHYS_PART_NAME: MOUNTING_HOLE_BRDMNT-MB_MOUNTING_HOLE; CDS_SEC: 1; DEVICE_TYPENAME: MOUNTING_HOLE_BRDMNT-MB_MOUNTING_HOLE; DRAWING: @P2597_C02_LIB.P2597_C02(SCH_1):PAGE33; NV_NAME: MB_MOUNTING_HOLE; PACK_TYPE: BRDMNT; PATH: I116; PHYS_PAGE: 33; ROT: 0; SEC: 1; SEC_TYPE: BRDMNT; VER: 2; XY: (-11050,1800)
MEC13 = MOUNTING_HOLE#1: CDS_LIB: mechanic; CDS_PART_NAME: MOUNTING_HOLE_BRDMNT-MB_MOUNTING_HOLE; CDS_PHYS_PART_NAME: MOUNTING_HOLE_BRDMNT-MB_MOUNTING_HOLE; CDS_SEC: 1; DEVICE_TYPENAME: MOUNTING_HOLE_BRDMNT-MB_MOUNTING_HOLE; DRAWING: @P2597_C02_LIB.P2597_C02(SCH_1):PAGE33; NV_NAME: MB_MOUNTING_HOLE; PACK_TYPE: BRDMNT; PATH: I117; PHYS_PAGE: 33; ROT: 0; SEC: 1; SEC_TYPE: BRDMNT; VER: 2; XY: (-11050,2400)
MEC14 = MOUNTING_HOLE#1: CDS_LIB: mechanic; CDS_PART_NAME: MOUNTING_HOLE_BRDMNT-MB_MOUNTING_HOLE; CDS_PHYS_PART_NAME: MOUNTING_HOLE_BRDMNT-MB_MOUNTING_HOLE; CDS_SEC: 1; DEVICE_TYPENAME: MOUNTING_HOLE_BRDMNT-MB_MOUNTING_HOLE; DRAWING: @P2597_C02_LIB.P2597_C02(SCH_1):PAGE33; NV_NAME: MB_MOUNTING_HOLE; PACK_TYPE: BRDMNT; PATH: I108; PHYS_PAGE: 33; ROT: 0; SEC: 1; SEC_TYPE: BRDMNT; VER: 2; XY: (-11050,1250)
MEC15 = MOUNTING_HOLE: CDS_LIB: mechanic; CDS_PART_NAME: MOUNTING_HOLE_X1-P1963_MOUNTING_HOLE_3.2; CDS_PHYS_PART_NAME: MOUNTING_HOLE_X1-P1963_MOUNTING_HOLE_3.2; CDS_SEC: 1; DEVICE_TYPENAME: MOUNTING_HOLE_X1-P1963_MOUNTING_HOLE_32; DRAWING: @P2597_C02_LIB.P2597_C02(SCH_1):PAGE33; NV_NAME: P1963_MOUNTING_HOLE_3.2; PACK_TYPE: X1; PATH: I149; PHYS_PAGE: 33; ROT: 0; SEC: 1; SEC_TYPE: X1; VER: 1; XY: (-9500,1800)
MEC16 = MOUNTING_HOLE: CDS_LIB: mechanic; CDS_PART_NAME: MOUNTING_HOLE_X1-P1963_MOUNTING_HOLE_3.2; CDS_PHYS_PART_NAME: MOUNTING_HOLE_X1-P1963_MOUNTING_HOLE_3.2; CDS_SEC: 1; DEVICE_TYPENAME: MOUNTING_HOLE_X1-P1963_MOUNTING_HOLE_32; DRAWING: @P2597_C02_LIB.P2597_C02(SCH_1):PAGE33; NV_NAME: P1963_MOUNTING_HOLE_3.2; PACK_TYPE: X1; PATH: I148; PHYS_PAGE: 33; ROT: 0; SEC: 1; SEC_TYPE: X1; VER: 1; XY: (-9500,1450)
MEC17 = MEC_STANDOFF2: ASSEMBLY: CVM_STANDOFF_TOP; CDS_LIB: mechanic; CDS_PART_NAME: MEC_STANDOFF2_SMD-STANDOFF_M3.0X4.25MM,320-1630-000; CDS_PHYS_PART_NAME: MEC_STANDOFF2_SMD-STANDOFF_M3.0X4.25MM,320-1630-000-320-1630-000; CDS_SEC: 1; DEVICE_TYPENAME: MEC_STANDOFF2_SMD-STANDOFF_M30X425MM320-1630-000-320-1630-000; DRAWING: @P2597_C02_LIB.P2597_C02(SCH_1):PAGE33; NV_NAME: STANDOFF_M3.0X4.25MM; NV_PN: 320-1630-000; PACK_TYPE: SMD; PATH: I113; PHYS_PAGE: 33; ROT: 2; SEC: 1; SKU: NO STUFF; VER: 1; XY: (-10550,6350)
MEC18 = MEC_STANDOFF2: ASSEMBLY: CVM_STANDOFF_TOP; CDS_LIB: mechanic; CDS_PART_NAME: MEC_STANDOFF2_SMD-STANDOFF_M3.0X4.25MM,320-1630-000; CDS_PHYS_PART_NAME: MEC_STANDOFF2_SMD-STANDOFF_M3.0X4.25MM,320-1630-000-320-1630-000; CDS_SEC: 1; DEVICE_TYPENAME: MEC_STANDOFF2_SMD-STANDOFF_M30X425MM320-1630-000-320-1630-000; DRAWING: @P2597_C02_LIB.P2597_C02(SCH_1):PAGE33; NV_NAME: STANDOFF_M3.0X4.25MM; NV_PN: 320-1630-000; PACK_TYPE: SMD; PATH: I97; PHYS_PAGE: 33; ROT: 2; SEC: 1; SKU: NO STUFF; VER: 1; XY: (-10550,5900)
MEC19 = MEC_STANDOFF2: ASSEMBLY: CVM_STANDOFF_TOP; CDS_LIB: mechanic; CDS_PART_NAME: MEC_STANDOFF2_SMD-STANDOFF_M3.0X4.25MM,320-1630-000; CDS_PHYS_PART_NAME: MEC_STANDOFF2_SMD-STANDOFF_M3.0X4.25MM,320-1630-000-320-1630-000; CDS_SEC: 1; DEVICE_TYPENAME: MEC_STANDOFF2_SMD-STANDOFF_M30X425MM320-1630-000-320-1630-000; DRAWING: @P2597_C02_LIB.P2597_C02(SCH_1):PAGE33; NV_NAME: STANDOFF_M3.0X4.25MM; NV_PN: 320-1630-000; PACK_TYPE: SMD; PATH: I114; PHYS_PAGE: 33; ROT: 2; SEC: 1; SKU: NO STUFF; VER: 1; XY: (-10550,5300)
MEC20 = MEC_STANDOFF2: ASSEMBLY: CVM_STANDOFF_TOP; CDS_LIB: mechanic; CDS_PART_NAME: MEC_STANDOFF2_SMD-STANDOFF_M3.0X4.25MM,320-1630-000; CDS_PHYS_PART_NAME: MEC_STANDOFF2_SMD-STANDOFF_M3.0X4.25MM,320-1630-000-320-1630-000; CDS_SEC: 1; DEVICE_TYPENAME: MEC_STANDOFF2_SMD-STANDOFF_M30X425MM320-1630-000-320-1630-000; DRAWING: @P2597_C02_LIB.P2597_C02(SCH_1):PAGE33; NV_NAME: STANDOFF_M3.0X4.25MM; NV_PN: 320-1630-000; PACK_TYPE: SMD; PATH: I115; PHYS_PAGE: 33; ROT: 2; SEC: 1; SKU: NO STUFF; VER: 1; XY: (-10550,4750)
MEC21 = MEC_STANDOFF2: ASSEMBLY: CVM_STANDOFF_BOT; CDS_LIB: mechanic; CDS_PART_NAME: MEC_STANDOFF2_SMD-STANDOFF_M3.0X3.0MM,320-0965-000; CDS_PHYS_PART_NAME: MEC_STANDOFF2_SMD-STANDOFF_M3.0X3.0MM,320-0965-000-320-0965-000; CDS_SEC: 1; DEVICE_TYPENAME: MEC_STANDOFF2_SMD-STANDOFF_M30X30MM320-0965-000-320-0965-000; DRAWING: @P2597_C02_LIB.P2597_C02(SCH_1):PAGE33; NV_NAME: STANDOFF_M3.0X3.0MM; NV_PN: 320-0965-000; PACK_TYPE: SMD; PATH: I153; PHYS_PAGE: 33; ROT: 2; SEC: 1; VER: 1; XY: (-9050,6350)
MEC22 = MEC_STANDOFF2: ASSEMBLY: CVM_STANDOFF_BOT; CDS_LIB: mechanic; CDS_PART_NAME: MEC_STANDOFF2_SMD-STANDOFF_M3.0X3.0MM,320-0965-000; CDS_PHYS_PART_NAME: MEC_STANDOFF2_SMD-STANDOFF_M3.0X3.0MM,320-0965-000-320-0965-000; CDS_SEC: 1; DEVICE_TYPENAME: MEC_STANDOFF2_SMD-STANDOFF_M30X30MM320-0965-000-320-0965-000; DRAWING: @P2597_C02_LIB.P2597_C02(SCH_1):PAGE33; NV_NAME: STANDOFF_M3.0X3.0MM; NV_PN: 320-0965-000; PACK_TYPE: SMD; PATH: I154; PHYS_PAGE: 33; ROT: 2; SEC: 1; VER: 1; XY: (-9050,5900)
MEC23 = MEC_STANDOFF2: ASSEMBLY: CVM_STANDOFF_BOT; CDS_LIB: mechanic; CDS_PART_NAME: MEC_STANDOFF2_SMD-STANDOFF_M3.0X3.0MM,320-0965-000; CDS_PHYS_PART_NAME: MEC_STANDOFF2_SMD-STANDOFF_M3.0X3.0MM,320-0965-000-320-0965-000; CDS_SEC: 1; DEVICE_TYPENAME: MEC_STANDOFF2_SMD-STANDOFF_M30X30MM320-0965-000-320-0965-000; DRAWING: @P2597_C02_LIB.P2597_C02(SCH_1):PAGE33; NV_NAME: STANDOFF_M3.0X3.0MM; NV_PN: 320-0965-000; PACK_TYPE: SMD; PATH: I155; PHYS_PAGE: 33; ROT: 2; SEC: 1; VER: 1; XY: (-9050,5300)
MEC24 = MEC_STANDOFF2: ASSEMBLY: CVM_STANDOFF_BOT; CDS_LIB: mechanic; CDS_PART_NAME: MEC_STANDOFF2_SMD-STANDOFF_M3.0X3.0MM,320-0965-000; CDS_PHYS_PART_NAME: MEC_STANDOFF2_SMD-STANDOFF_M3.0X3.0MM,320-0965-000-320-0965-000; CDS_SEC: 1; DEVICE_TYPENAME: MEC_STANDOFF2_SMD-STANDOFF_M30X30MM320-0965-000-320-0965-000; DRAWING: @P2597_C02_LIB.P2597_C02(SCH_1):PAGE33; NV_NAME: STANDOFF_M3.0X3.0MM; NV_PN: 320-0965-000; PACK_TYPE: SMD; PATH: I156; PHYS_PAGE: 33; ROT: 2; SEC: 1; VER: 1; XY: (-9050,4750)
Q7 = Q_FET_N_ENH#2: ASSEMBLY: BUTTONS; CDS_LIB: discrete; CDS_PART_NAME: Q_FET_N_ENH_SOT23_1G1D1S-FDV301N,25V,-1000MOHM@10V / 4000MOHM@4.5V / -1000MOHM@2.5V,0.22A,0.5A,8V,0.35W,[ ]@10V / [ ]@4.5V / [A; CDS_PHYS_PART_NAME: Q_FET_N_ENH_SOT23_1G1D1S-FDV301N,25V,-1000MOHM@10V / 4000MOHM@4.5V / -1000MOHM@2.5V,0.22A,0.5A,8V,0.35W,[ ]@10V / [ ]@4.5V / [B; CDS_SEC: 1; CONTINUOUS_CURRENT: 0.22A; CaptureCellPackProp: Q_FET_N_ENH__sym_2##2; DEVICE_TYPENAME: Q_FET_N_ENH_SOT23_1G1D1S-FDV301N25V-1000MOHM10V4000MOHM45V-1000MOHM25V022A05A8V035W10V45VB; DRAWING: @P2597_C02_LIB.P2597_C02(SCH_1):PAGE33; MAX_CURRENT: 0.5A; MAX_VOLTAGE: 25V; MAX_WATTAGE: 0.35W; NV_NAME: FDV301N; NV_PN: 300-0494-000; PACK_TYPE: SOT23_1G1D1S; PATH: I77; PHYS_PAGE: 33; Q_G: [ ]@10V / [ ]@4.5V / [ ]@2.5V; ROT: 0; R_DS_ON: -1000mohm@10V / 4000mohm@4.5V / -1000mohm@2.5V; SEC: 1; SEC_TYPE: SOT23_1G1D1S; VER: 2; V_BE_GS: 8V; XY: (-6850,1450)
Q15 = Q_FET_N_ENH#2: ASSEMBLY: BUTTONS; CDS_LIB: discrete; CDS_PART_NAME: Q_FET_N_ENH_SOT23_1G1D1S-FDV301N,25V,-1000MOHM@10V / 4000MOHM@4.5V / -1000MOHM@2.5V,0.22A,0.5A,8V,0.35W,[ ]@10V / [ ]@4.5V / [A; CDS_PHYS_PART_NAME: Q_FET_N_ENH_SOT23_1G1D1S-FDV301N,25V,-1000MOHM@10V / 4000MOHM@4.5V / -1000MOHM@2.5V,0.22A,0.5A,8V,0.35W,[ ]@10V / [ ]@4.5V / [B; CDS_SEC: 1; CONTINUOUS_CURRENT: 0.22A; CaptureCellPackProp: Q_FET_N_ENH__sym_2##2; DEVICE_TYPENAME: Q_FET_N_ENH_SOT23_1G1D1S-FDV301N25V-1000MOHM10V4000MOHM45V-1000MOHM25V022A05A8V035W10V45VB; DRAWING: @P2597_C02_LIB.P2597_C02(SCH_1):PAGE33; MAX_CURRENT: 0.5A; MAX_VOLTAGE: 25V; MAX_WATTAGE: 0.35W; NV_NAME: FDV301N; NV_PN: 300-0494-000; PACK_TYPE: SOT23_1G1D1S; PATH: I69; PHYS_PAGE: 33; Q_G: [ ]@10V / [ ]@4.5V / [ ]@2.5V; ROT: 0; R_DS_ON: -1000mohm@10V / 4000mohm@4.5V / -1000mohm@2.5V; SEC: 1; SEC_TYPE: SOT23_1G1D1S; VER: 2; V_BE_GS: 8V; XY: (-4300,950)
Q16 = Q_FET_N_ENH#2: ASSEMBLY: BUTTONS; CDS_LIB: discrete; CDS_PART_NAME: Q_FET_N_ENH_SOT23_1G1D1S-FDV301N,25V,-1000MOHM@10V / 4000MOHM@4.5V / -1000MOHM@2.5V,0.22A,0.5A,8V,0.35W,[ ]@10V / [ ]@4.5V / [A; CDS_PHYS_PART_NAME: Q_FET_N_ENH_SOT23_1G1D1S-FDV301N,25V,-1000MOHM@10V / 4000MOHM@4.5V / -1000MOHM@2.5V,0.22A,0.5A,8V,0.35W,[ ]@10V / [ ]@4.5V / [B; CDS_SEC: 1; CONTINUOUS_CURRENT: 0.22A; CaptureCellPackProp: Q_FET_N_ENH__sym_2##2; DEVICE_TYPENAME: Q_FET_N_ENH_SOT23_1G1D1S-FDV301N25V-1000MOHM10V4000MOHM45V-1000MOHM25V022A05A8V035W10V45VB; DRAWING: @P2597_C02_LIB.P2597_C02(SCH_1):PAGE33; MAX_CURRENT: 0.5A; MAX_VOLTAGE: 25V; MAX_WATTAGE: 0.35W; NV_NAME: FDV301N; NV_PN: 300-0494-000; PACK_TYPE: SOT23_1G1D1S; PATH: I55; PHYS_PAGE: 33; Q_G: [ ]@10V / [ ]@4.5V / [ ]@2.5V; ROT: 0; R_DS_ON: -1000mohm@10V / 4000mohm@4.5V / -1000mohm@2.5V; SEC: 1; SEC_TYPE: SOT23_1G1D1S; VER: 2; V_BE_GS: 8V; XY: (-4300,1450)
R14 = R: ASSEMBLY: BUTTONS; CDS_LIB: discrete; CDS_PART_NAME: R_0402-0OHM,0.05 OHM,62.5MW,195-2655-000; CDS_PHYS_PART_NAME: R_0402-0OHM,0.05 OHM,62.5MW,195-2655-000-0OHM,195-2655-000; CDS_SEC: 1; DEVICE_TYPENAME: R_0402-0OHM005OHM625MW195-2655-000-0OHM195-2655-000; DRAWING: @P2597_C02_LIB.P2597_C02(SCH_1):PAGE33; MAX_WATTAGE: 62.5mW; NV_PN: 195-2655-000; PATH: I34; PHYS_PAGE: 33; ROT: 0; SEC: 1; SIGNAL_MODEL: nv_res; TOL: 0.05 ohm; VER: 1; XY: (-3200,3600)
R34 = R: ASSEMBLY: BUTTONS; CDS_LIB: discrete; CDS_PART_NAME: R_0402-0OHM,0.05 OHM,62.5MW,195-2655-000; CDS_PHYS_PART_NAME: R_0402-0OHM,0.05 OHM,62.5MW,195-2655-000-0OHM,195-2655-000; CDS_SEC: 1; DEVICE_TYPENAME: R_0402-0OHM005OHM625MW195-2655-000-0OHM195-2655-000; DRAWING: @P2597_C02_LIB.P2597_C02(SCH_1):PAGE33; MAX_WATTAGE: 62.5mW; NV_PN: 195-2655-000; PATH: I100; PHYS_PAGE: 33; ROT: 0; SEC: 1; SIGNAL_MODEL: nv_res; TOL: 0.05 ohm; VER: 1; XY: (-3200,4600)
R59 = R: ASSEMBLY: BUTTONS; CDS_LIB: discrete; CDS_PART_NAME: R_0402-0OHM,0.05 OHM,62.5MW,195-2655-000; CDS_PHYS_PART_NAME: R_0402-0OHM,0.05 OHM,62.5MW,195-2655-000-0OHM,195-2655-000; CDS_SEC: 1; DEVICE_TYPENAME: R_0402-0OHM005OHM625MW195-2655-000-0OHM195-2655-000; DRAWING: @P2597_C02_LIB.P2597_C02(SCH_1):PAGE33; MAX_WATTAGE: 62.5mW; NV_PN: 195-2655-000; PATH: I31; PHYS_PAGE: 33; ROT: 0; SEC: 1; SIGNAL_MODEL: nv_res; TOL: 0.05 ohm; VER: 1; XY: (-3200,5600)
R60 = R#1: ASSEMBLY: BUTTONS; CDS_LIB: discrete; CDS_PART_NAME: R_0402-330OHM,5 %,62.5MW,195-0569-000; CDS_PHYS_PART_NAME: R_0402-330OHM,5 %,62.5MW,195-0569-000-195-0569-000,330OHM; CDS_SEC: 1; CHIPS_PART_NAME: R; DEVICE_TYPENAME: R_0402-330OHM5625MW195-0569-000-195-0569-000330OHM; DRAWING: @P2597_C02_LIB.P2597_C02(SCH_1):PAGE33; MAX_WATTAGE: 62.5mW; NV_PN: 195-0569-000; PATH: I76; PHYS_PAGE: 33; ROT: 0; SEC: 1; SIGNAL_MODEL: nv_res; TOL: 5%; VER: 2; XY: (-6700,1950)
R86 = R: ASSEMBLY: BUTTONS; CDS_LIB: discrete; CDS_PART_NAME: R_0402-0OHM,0.05 OHM,62.5MW,195-2655-000; CDS_PHYS_PART_NAME: R_0402-0OHM,0.05 OHM,62.5MW,195-2655-000-0OHM,195-2655-000; CDS_SEC: 1; DEVICE_TYPENAME: R_0402-0OHM005OHM625MW195-2655-000-0OHM195-2655-000; DRAWING: @P2597_C02_LIB.P2597_C02(SCH_1):PAGE33; MAX_WATTAGE: 62.5mW; NV_PN: 195-2655-000; PATH: I35; PHYS_PAGE: 33; ROT: 0; SEC: 1; SIGNAL_MODEL: nv_res; TOL: 0.05 ohm; VER: 1; XY: (-3250,6950)
R101 = R#1: ASSEMBLY: BUTTONS; CDS_LIB: discrete; CDS_PART_NAME: R_0402-330OHM,5 %,62.5MW,195-0569-000; CDS_PHYS_PART_NAME: R_0402-330OHM,5 %,62.5MW,195-0569-000-195-0569-000,330OHM; CDS_SEC: 1; CHIPS_PART_NAME: R; DEVICE_TYPENAME: R_0402-330OHM5625MW195-0569-000-195-0569-000330OHM; DRAWING: @P2597_C02_LIB.P2597_C02(SCH_1):PAGE33; MAX_WATTAGE: 62.5mW; NV_PN: 195-0569-000; PATH: I54; PHYS_PAGE: 33; ROT: 0; SEC: 1; SIGNAL_MODEL: nv_res; TOL: 5%; VER: 2; XY: (-4150,1950)
R104 = R#1: ASSEMBLY: BUTTONS; CDS_LIB: discrete; CDS_PART_NAME: R_0402-330OHM,5 %,62.5MW,195-0569-000; CDS_PHYS_PART_NAME: R_0402-330OHM,5 %,62.5MW,195-0569-000-195-0569-000,330OHM; CDS_SEC: 1; CHIPS_PART_NAME: R; DEVICE_TYPENAME: R_0402-330OHM5625MW195-0569-000-195-0569-000330OHM; DRAWING: @P2597_C02_LIB.P2597_C02(SCH_1):PAGE33; MAX_WATTAGE: 62.5mW; NV_PN: 195-0569-000; PATH: I126; PHYS_PAGE: 33; ROT: 0; SEC: 1; SIGNAL_MODEL: nv_res; TOL: 5%; VER: 2; XY: (-2950,1950)
S1 = SW_SPST_PB: ANGLE: 0; ASSEMBLY: BUTTONS; CDS_LIB: electro_mechanic; CDS_PART_NAME: SW_SPST_PB_SMD_4-DTSMW67N,N/A,N/A,0,YES,N/A,N/A,12V,50MA,280-0060-000; CDS_PHYS_PART_NAME: SW_SPST_PB_SMD_4-DTSMW67N,N/A,N/A,0,YES,N/A,N/A,12V,50MA,280-0060-000-280-0060-000; CDS_SEC: 1; DEVICE_TYPENAME: SW_SPST_PB_SMD_4-DTSMW67NNANA0YESNANA12V50MA280-0060-000-280-0060-000; DRAWING: @P2597_C02_LIB.P2597_C02(SCH_1):PAGE33; GENDER: N/A; LATCHING: N/A; MAX_CURRENT: 50MA; MAX_VOLTAGE: 12V; NV_NAME: DTSMW67N; NV_PN: 280-0060-000; PACK_TYPE: SMD_4; PATH: I10; PHYS_PAGE: 33; PITCH: N/A; REFLOW: YES; ROT: 0; SEC: 1; SHROUDED: N/A; VER: 1; XY: (-5450,3550)
S2 = SW_SPST_PB: ANGLE: 0; ASSEMBLY: BUTTONS; CDS_LIB: electro_mechanic; CDS_PART_NAME: SW_SPST_PB_SMD_4-DTSMW67N,N/A,N/A,0,YES,N/A,N/A,12V,50MA,280-0060-000; CDS_PHYS_PART_NAME: SW_SPST_PB_SMD_4-DTSMW67N,N/A,N/A,0,YES,N/A,N/A,12V,50MA,280-0060-000-280-0060-000; CDS_SEC: 1; DEVICE_TYPENAME: SW_SPST_PB_SMD_4-DTSMW67NNANA0YESNANA12V50MA280-0060-000-280-0060-000; DRAWING: @P2597_C02_LIB.P2597_C02(SCH_1):PAGE33; GENDER: N/A; LATCHING: N/A; MAX_CURRENT: 50MA; MAX_VOLTAGE: 12V; NV_NAME: DTSMW67N; NV_PN: 280-0060-000; PACK_TYPE: SMD_4; PATH: I106; PHYS_PAGE: 33; PITCH: N/A; REFLOW: YES; ROT: 0; SEC: 1; SHROUDED: N/A; VER: 1; XY: (-5450,4550)
S3 = SW_SPST_PB: ANGLE: 0; ASSEMBLY: BUTTONS; CDS_LIB: electro_mechanic; CDS_PART_NAME: SW_SPST_PB_SMD_4-DTSMW67N,N/A,N/A,0,YES,N/A,N/A,12V,50MA,280-0060-000; CDS_PHYS_PART_NAME: SW_SPST_PB_SMD_4-DTSMW67N,N/A,N/A,0,YES,N/A,N/A,12V,50MA,280-0060-000-280-0060-000; CDS_SEC: 1; DEVICE_TYPENAME: SW_SPST_PB_SMD_4-DTSMW67NNANA0YESNANA12V50MA280-0060-000-280-0060-000; DRAWING: @P2597_C02_LIB.P2597_C02(SCH_1):PAGE33; GENDER: N/A; LATCHING: N/A; MAX_CURRENT: 50MA; MAX_VOLTAGE: 12V; NV_NAME: DTSMW67N; NV_PN: 280-0060-000; PACK_TYPE: SMD_4; PATH: I26; PHYS_PAGE: 33; PITCH: N/A; REFLOW: YES; ROT: 0; SEC: 1; SHROUDED: N/A; VER: 1; XY: (-5450,5550)
S4 = SW_SPST_PB: ANGLE: 0; ASSEMBLY: BUTTONS; CDS_LIB: electro_mechanic; CDS_PART_NAME: SW_SPST_PB_SMD_4-DTSMW67N,N/A,N/A,0,YES,N/A,N/A,12V,50MA,280-0060-000; CDS_PHYS_PART_NAME: SW_SPST_PB_SMD_4-DTSMW67N,N/A,N/A,0,YES,N/A,N/A,12V,50MA,280-0060-000-280-0060-000; CDS_SEC: 1; DEVICE_TYPENAME: SW_SPST_PB_SMD_4-DTSMW67NNANA0YESNANA12V50MA280-0060-000-280-0060-000; DRAWING: @P2597_C02_LIB.P2597_C02(SCH_1):PAGE33; GENDER: N/A; LATCHING: N/A; MAX_CURRENT: 50MA; MAX_VOLTAGE: 12V; NV_NAME: DTSMW67N; NV_PN: 280-0060-000; PACK_TYPE: SMD_4; PATH: I12; PHYS_PAGE: 33; PITCH: N/A; REFLOW: YES; ROT: 0; SEC: 1; SHROUDED: N/A; VER: 1; XY: (-5450,6900)

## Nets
1V8_IO_PG: Q15.1(G) ; also on sheet 5
GND: C29.2 C35.2 C46.2 C50.2 C516.2 D2.2(2A) D3.2(2A) D4.2(2A) D6.2(2A) D14.2(2A) D15.2(2A) J20.1 J20.3 J20.5 J20.7 J20.9 J20.10 MEC1.1 MEC1.2 MEC1.3 MEC1.4 MEC1.5 MEC1.6 MEC1.7 MEC1.8 MEC2.1 MEC2.2 MEC2.3 MEC2.4 MEC2.5 MEC2.6 MEC2.7 MEC2.8 MEC13.1 MEC13.2 MEC13.3 MEC13.4 MEC13.5 MEC13.6 MEC13.7 MEC13.8 MEC14.1 MEC14.2 MEC14.3 MEC14.4 MEC14.5 MEC14.6 MEC14.7 MEC14.8 MEC15.1(GND) MEC16.1(GND) MEC17.1A MEC17.1B MEC18.1A MEC18.1B MEC19.1A MEC19.1B MEC20.1A MEC20.1B MEC21.1A MEC21.1B MEC22.1A MEC22.1B MEC23.1A MEC23.1B MEC24.1A MEC24.1B Q7.2(S) Q15.2(S) R147.2 S1.2 S1.3 S2.2 S2.3 S3.2 S3.3 S4.2 S4.3 U10.TP(PAD) ; also on sheet 3 4 5 6 7 9 10 11 12 13 14 15 16 17 18 19 20 21 22 23 24 25 26 30
VDD_1V8_IO_FILTER_N: C89.2 C91.2 R160.1 U10.14(VIN2N)
VDD_1V8_IO_FILTER_P: C87.1 C89.1 R151.1 R153.1 U10.15(VIN2P)
VDD_1V8_IO_N: R160.2 ; also on sheet 5
VDD_1V8_IO_P: R153.2 ; also on sheet 5
VDD_3V3_IO_SLP_FILTER_N: C95.2 C99.2 R171.1 U10.11(VIN1N)
VDD_3V3_IO_SLP_FILTER_P: C94.2 C99.1 R163.1 R170.1 U10.12(VIN1P)
VDD_3V3_IO_SLP_N: R171.2 ; also on sheet 5
VDD_3V3_IO_SLP_P: R170.2 ; also on sheet 5
VDD_3V3_SYS: C516.1 CR1.2(A) CR2.2(A) D14.1(1C) J4.1 U10.4(VS) ; also on sheet 3 4 5 6 12 13 17 18 19 23 24 25
VDD_3V3_SYS_PG: Q16.1(G) ; also on sheet 6
VDD_3V3_SYS_PG_AND: Q15.3(D) Q16.2(S)
VDD_3V3_SYS_PG_Q: D15.1(1C) Q16.3(D) R101.2 R104.2
VDD_3V3_SYS_PG_Q_PNL: J4.2 R104.1
VDD_3V3_SYS_PG_QQ: CR2.1(C) R101.1
VDD_M2_IN_N: R139.2 ; also on sheet 24
VDD_M2_IN_P: R140.2 ; also on sheet 24
VDD_M2_IO_FILT_N: C78.2 C83.1 R139.1 U10.1(VIN3N)
VDD_M2_IO_FILT_P: C78.1 C84.1 R140.1 R141.1 U10.2(VIN3P)
D_FORCE_OFF_L: J20.4 ; also on sheet 6 12
FORCE_RECOVERY_L: R59.2 ; also on sheet 30
FORCE_RECOVERY_R_L: C46.1 D4.1(1C) J20.6 R59.1 S3.1 S3.4 ; also on sheet 12
I2C_GP1_CLK_3V3: R152.1 U10.6(SCL) ; also on sheet 3 12 13 17 18 19 30
I2C_GP1_DAT_3V3: U10.7(SDA) ; also on sheet 3 12 13 17 18 19 30
INA_3_A0: R152.2 U10.5(A0)
LED_VDD_CORE: Q7.1(G) ; also on sheet 12
PMGND3: C83.2 C84.2 C87.2 C91.1 C94.1 C95.1 R141.2 R147.1 R151.2 R163.2 U10.3(GND)
POWER_BTN: R86.2 ; also on sheet 15
POWER_BTN_R: C50.1 D6.1(1C) J20.2 R86.1 S4.1 S4.4 ; also on sheet 12
RESET_IN_L: R14.2 ; also on sheet 30
RESET_IN_R_L: C29.1 D2.1(1C) J20.8 R14.1 S1.1 S1.4 ; also on sheet 12
SLEEP: R34.2 ; also on sheet 18 30
SLEEP_R: C35.1 D3.1(1C) R34.1 S2.1 S2.4
SNN_CRIT_3: U10.9(CRITICAL*)
SNN_PM2_PV_1: U10.10(PV)
SNN_PM2_TC_1: U10.13(TC)
SNN_PM2_VPU_1: U10.16(VPU)
SNN_WARN_3: U10.8(WARNING*)
SOC_REG_EN_Q: Q7.3(D) R60.2
SOC_REG_EN_QQ: CR1.1(C) R60.1

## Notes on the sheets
sheet 1
- A
- B
- C
- D
- E
- F
- G
- H
- POWER
- MODULE MOUNTING STANDOFFS
- Top Side      Botseltom Side
- 1
- 1
- RECOVERY
- 2
- 2
- VOL DOWN
- 3
- 3
- FOUR CORNER
- RESET
- miniITX MOUNTING HOLES
- CAD NOTE:
- Please place LEDs near the
- power button in the front
- label slik per text below
- SOC EN
- POWER
- 4
- 4
- Antenna bracket
- mount
- 5
- 5
- NVIDIA CORPORATION
- 2701 SAN TOMAS EXPRESSWAY
- ASSEMBLY
- <ASSEMBLY_DESCRIPTION>
- SANTA CLARA, CA 95050, USA
- PAGE DETAIL
- Buttons and Mechanical
- NV_PN
- 600-82597-BASE-900
- ALL NVIDIA DESIGN SPECIFICATIONS, REFERENCE SPECIFICATIONS, REFERENCE BOARDS, FILES, DRAWINGS, DIAGNOSTICS, LISTS AND OTHER DOCUMENTS OR INFORMATION (TOGETHER AND SEPARATELY, 'MATERIALS') ARE BEING PROVIDED 'AS IS'. THE MATERIALS MAY
- CONTAIN KNOWN AND UNKNOWN VIOLATIONS OR DEVIATIONS OF INDUSTRY STANDARDS AND SPECIFICATIONS. NVIDIA MAKES NO WARRANTIES, EXPRESSED, IMPLIED, STATUTORY OR OTHERWISE WITH RESPECT TO THE MATERIALS OR OTHERWISE, AND EXPRESSLY DISCLAIMS ALL
- PCB REV
- P2597-C02
- PAGE
- 33 OF 34
- IMPLIED WARRANTIES INCLUDING, WITHOUT LIMITATION, THE WARRANTIES OF DESIGN, OF NONINFRINGEMENT, MERCHANTABILITY OR FITNESS FOR A PARTICULAR PURPOSE, OR ARISING FROM A COURSE OF DEALING, TRADE USAGE, TRADE PRACTICE, OR INDUSTRY STANDARDS.
- BOM REV
- A
- DATE
- 23-OCT-2017
- A
- B
- C
- D
- E
- F
- G
- H
sheet 2
- A
- B
- C
- D
- E
- F
- G
- H
- POWER MONITORS II
- 1
- 1
- 2
- 2
- 3V3 RUN RAIL
- 1.8V SYSTEM
- I2C Gen 2 : 7'h43
- 3
- 3
- M.2 3.3V
- 4
- 4
- 5
- 5
- NVIDIA CORPORATION
- 2701 SAN TOMAS EXPRESSWAY
- ASSEMBLY
- <ASSEMBLY_DESCRIPTION>
- SANTA CLARA, CA 95050, USA
- PAGE DETAIL
- Power Monitor II
- NV_PN
- 600-82597-BASE-900
- ALL NVIDIA DESIGN SPECIFICATIONS, REFERENCE SPECIFICATIONS, REFERENCE BOARDS, FILES, DRAWINGS, DIAGNOSTICS, LISTS AND OTHER DOCUMENTS OR INFORMATION (TOGETHER AND SEPARATELY, 'MATERIALS') ARE BEING PROVIDED 'AS IS'. THE MATERIALS MAY
- CONTAIN KNOWN AND UNKNOWN VIOLATIONS OR DEVIATIONS OF INDUSTRY STANDARDS AND SPECIFICATIONS. NVIDIA MAKES NO WARRANTIES, EXPRESSED, IMPLIED, STATUTORY OR OTHERWISE WITH RESPECT TO THE MATERIALS OR OTHERWISE, AND EXPRESSLY DISCLAIMS ALL
- PCB REV
- P2597-C02
- PAGE
- 32 OF 34
- IMPLIED WARRANTIES INCLUDING, WITHOUT LIMITATION, THE WARRANTIES OF DESIGN, OF NONINFRINGEMENT, MERCHANTABILITY OR FITNESS FOR A PARTICULAR PURPOSE, OR ARISING FROM A COURSE OF DEALING, TRADE USAGE, TRADE PRACTICE, OR INDUSTRY STANDARDS.
- BOM REV
- A
- DATE
- 23-OCT-2017
- A
- B
- C
- D
- E
- F
- G
- H
